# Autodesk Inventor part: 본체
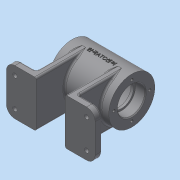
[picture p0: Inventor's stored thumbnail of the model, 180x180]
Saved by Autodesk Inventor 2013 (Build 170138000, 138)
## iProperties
Created: 2017-02
Part Number: 본체
Material: 일반
Document SubType Name: Modeling
Designer: dgall
Density: 1 g/cm^3
Author: dgall
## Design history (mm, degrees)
sketch "스케치1"
  geometry: L1 (0, 0)-(70, 0); L2 (0, 16)-(11.7, 16); L3 (12, 15.7)-(12, 14); L4 (12, 14)-(15, 14); L5 (15, 14)-(15, 19); L6 (18, 22)-(52, 22); L7 (55, 19)-(55, 14); L8 (55, 14)-(58, 14); L9 (58, 14)-(58, 15.7); L10 (58.3, 16)-(70, 16); L11 (0, 16)-(0, 27); L12 (0, 27)-(70, 27); L13 (70, 27)-(70, 16); A1 r 0.3 centre (11.7, 15.7) between (12, 15.7) and (11.7, 16); A2 r 0.3 centre (58.3, 15.7) between (58.3, 16) and (58, 15.7); A3 r 3 centre (52, 19) between (55, 19) and (52, 22); A4 r 3 centre (18, 19) between (18, 22) and (15, 19); 4 further points
  constraints: 26 end point, 8 parallel, 8 point on circle, 8 point on line, 8 tangent, 4 centre point, 3 perpendicular, 2 equal radius, 2 vertical alignment, 1 collinear, 1 horizontal
  dimensions: "d0" = 70 distance of L1.start L1.end; "d4" = 28 diameter of L8 L1; "d5" = 32 diameter of L10 L1; "d6" = 12 distance of point (58, 16) L10.end; "d7" = 12 distance of L2.start point (12, 16); "d8" = 32 diameter of L2 L1; "d9" = 28 diameter of L4 L1; "d10" = 40 distance of point (15, 22) point (55, 22); "d11" = 44 diameter of L6 L1; "d12" = 3 distance of L3.end L4.end; "d13" = 54 diameter of L12 L1; "d14" = 0.3 radius of A1; "d15" = 3 radius of A3
revolve "회전1" sketch "스케치1" stored, may be unused: angle "d16" = 90 deg
sketch "스케치2" dims "d17" = 42
  geometry: C1 r 16 at (0, 0) reference; C2 r 27 at (0, 0) reference; 2 further points
  constraints: 2 vertical alignment, 1 coincident, 2 other
hole "구멍1" sketch "스케치2" at (0, 21) diameter "d19" = 3.242; stored, may be unused: countersink angle "d23" = 90 deg, drill point angle "d25" = 118 deg; dims "d20" = 8, "d21" = 4, "d22" = 2, "d24" = 10
sketch "스케치3" dims "d29" = 42
  geometry: C1 r 27 at (0, 0) reference; C2 r 16 at (0, 0) reference; 2 further points
  constraints: 2 vertical alignment, 1 coincident, 2 other
hole "구멍2" sketch "스케치3" at (0, 21) diameter "d31" = 3.242; stored, may be unused: countersink angle "d35" = 90 deg, drill point angle "d37" = 118 deg; dims "d32" = 8, "d33" = 4, "d34" = 2, "d36" = 10
node "작업 평면1"
sketch "스케치4"
  geometry: L1 (0, 27)-(0, -27) reference; L2 (-87, 27)-(17, 27); L3 (-87, 27)-(-87, -27); L4 (-87, -27)-(17, -27); L5 (17, -27)-(17, 27); L6 (0, 27)-(-70, 27) reference; 5 further points
  constraints: 8 end point, 4 midpoint, 3 perpendicular, 1 horizontal alignment, 1 parallel, 1 vertical alignment
  dimensions: "d42" = 104 distance of L2.start L2.end; "d44" = 54 distance of L2.start L3.end
extrude "돌출1" join sketch "스케치4" distance "d45" = 8; taper "d46" = 0 deg
sketch "스케치5"
  geometry: L1 (-17, -27)-(87, -27) reference; L2 (87, 27)-(-17, 27) reference; L3 (35, 27)-(35, -27); L4 (18, 27)-(18, -27); L5 (52, 27)-(52, -27); 1 further point
  constraints: 6 end point, 4 point on line, 2 midpoint, 1 parallel, 1 perpendicular
  dimensions: "d47" = 17 distance between parallel lines of L3 L4; "d48" = 17 distance between parallel lines of L5 L3
extrude "돌출2" cut sketch "스케치5" stored distance "d49" = 8; taper "d50" = 0 deg
fillet "모깎기1" dims "d51" = 10
sketch "스케치6" dims "d52" = 9
  geometry: L1 (79.598, 21.5)-(82.196, 17); L2 (82.196, 17)-(79.598, 12.5); L3 (79.598, 12.5)-(74.402, 12.5); L4 (74.402, 12.5)-(71.804, 17); L5 (71.804, 17)-(74.402, 21.5); L6 (74.402, 21.5)-(79.598, 21.5); A1 r 10 centre (77, 17) between (87, 17) and (77, 27) reference; 4 further points
  constraints: 12 end point, 2 coincident, 2 vertical alignment, 1 midpoint, 15 other
extrude "돌출3" cut sketch "스케치6" distance "d54" = 3; taper "d55" = 0 deg
hole "구멍3" diameter "d58" = 5; stored, may be unused: countersink angle "d62" = 90 deg, drill point angle "d64" = 118 deg; dims "d56" = 10, "d57" = 10, "d59" = 8, "d60" = 4, "d61" = 2, "d63" = 10
sketch "스케치7"
  geometry: L1 (77, 27)-(52, 27) reference; L2 (52, 27)-(52, -27) reference; L3 (52, -27)-(77, -27) reference; L4 (60, 27)-(60, -27); 1 further point
  constraints: 2 end point, 2 point on line, 1 perpendicular
  dimensions: "d71" = 8 distance between parallel lines of L4 L2
extrude "돌출4" join sketch "스케치7" stored distance "d72" = 3; taper "d73" = 0 deg
sketch "스케치8"
  geometry: L1 (-7, -27)-(18, -27) reference; L2 (18, -27)-(18, 27) reference; L3 (18, 27)-(-7, 27) reference; L4 (10, 27)-(10, -27); 1 further point
  constraints: 2 end point, 2 point on line, 1 perpendicular
  dimensions: "d74" = 8 distance between parallel lines of L4 L2
extrude "돌출5" join sketch "스케치8" stored distance "d75" = 3; taper "d76" = 0 deg
fillet "모깎기2" dims "d77" = 2
node "작업 평면2"
sketch "스케치9"
  geometry: C1 r 5 at (-25, 0); 1 further point
  constraints: 1 centre point, 1 horizontal alignment
  dimensions: "d79" = 10 diameter of C1; "d81" = 25 distance of point (0, 0) C1.centre
extrude "돌출6" join sketch "스케치9" stored distance "d82" = 3; taper "d83" = 0 deg
hole "구멍4" diameter "d86" = 5.188; stored, may be unused: countersink angle "d90" = 90 deg, drill point angle "d92" = 118 deg; dims "d84" = 10, "d85" = 10, "d87" = 20, "d88" = 4, "d89" = 2, "d91" = 10
fillet "모깎기3" dims "d93" = 2
node "작업 평면3"
sketch "스케치10"
  geometry: L1 (0, 0)-(16.339, -25.16); L2 (0, 0)-(0, -27); A1 r 27 centre (0, 0) between (-23.276, -13.683) and (23.276, -13.683) reference
  constraints: 4 end point, 1 point on circle
  dimensions: "d95" = 33 deg angle of L1 L2; "d96" = 30 distance of L1.start L1.end
node "작업 평면4"
sketch "스케치11"
  geometry: C1 r 6 at (0, 0); 1 further point
  constraints: 1 centre point, 1 horizontal alignment
  dimensions: "d97" = 12 diameter of C1; "d99" = 35 distance of C1.centre point (-35, 0)
extrude "돌출7" join sketch "스케치11" stored distance "d100" = 3; taper "d101" = 0 deg
fillet "모깎기4" dims "d102" = 2
hole "구멍5" diameter "d105" = 5.188; stored, may be unused: countersink angle "d109" = 90 deg, drill point angle "d111" = 118 deg; dims "d103" = 10, "d104" = 10, "d106" = 20, "d107" = 4, "d108" = 2, "d110" = 10
chamfer "모따기1" distance "d112" = 1; stored, may be unused: second distance "d113" = 2, angle "d114" = 45 deg
node "작업 평면5"
sketch "스케치12"
  geometry: L1 (0, 27)-(70, 27) reference; 2 further points
  constraints: 1 other
  dimensions: "d116" = 35 distance of point (35, 0) point (0, 0); "d117" = 27 distance from line of point (35, 0) L1
feature "엠보싱1" sketch "스케치12" dims "d118" = 0.5, "d119" = 0
node "솔리드1"
pattern_circular "원형 패턴1" dims angle "d27" = 360 deg
pattern_circular "원형 패턴2" dims angle "d39" = 360 deg
pattern_linear "직사각형 패턴1" dims "d67" = 34
pattern_linear "직사각형 패턴2" dims "d70" = 84
other parameters: "d78" = 32, "d94" = -35
